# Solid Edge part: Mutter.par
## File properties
Sűrűség: 0,000 kg/m^3
Pontosság: 0,990
Author: ahadarics
Last saved by: ahadarics
Revision: 77
Username: ahadarics
Dokumentum tartalom típus: 0
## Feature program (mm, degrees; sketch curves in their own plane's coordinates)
base feature "unnamed BaseFeature 1"
thread "unnamed Thread 1"
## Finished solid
Body 1: solid body, 23 faces, 46 edges, 24 vertices.
  Faces by surface: cone 14, plane 8, cylinder 1
  Edges by curve: spline 24, circle 16, line 6
Bounding box of the edges (mm): 7.000 x 21.939 x 19.000, from (0, -10.9697, -9.5) to (7, 10.9697, 9.5).
Cylindrical faces by radius (mm): R5.3235 x1
Conical faces (half-angle, radius in mm at the cone's reference point): 60 deg R5.6618 x2, 60 deg R10.2348 x12
Planar faces by outward normal: +x 1, +z 1, -x 1, -z 1, oblique 4
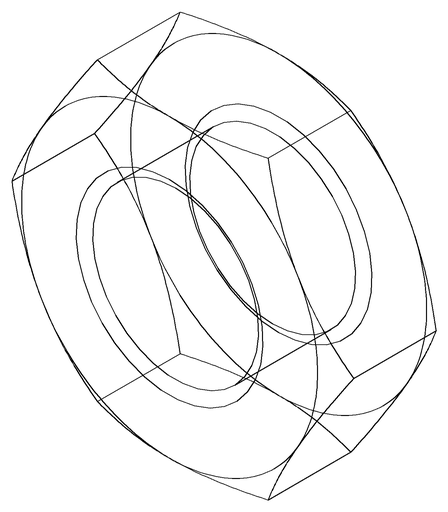
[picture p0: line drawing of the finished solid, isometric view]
